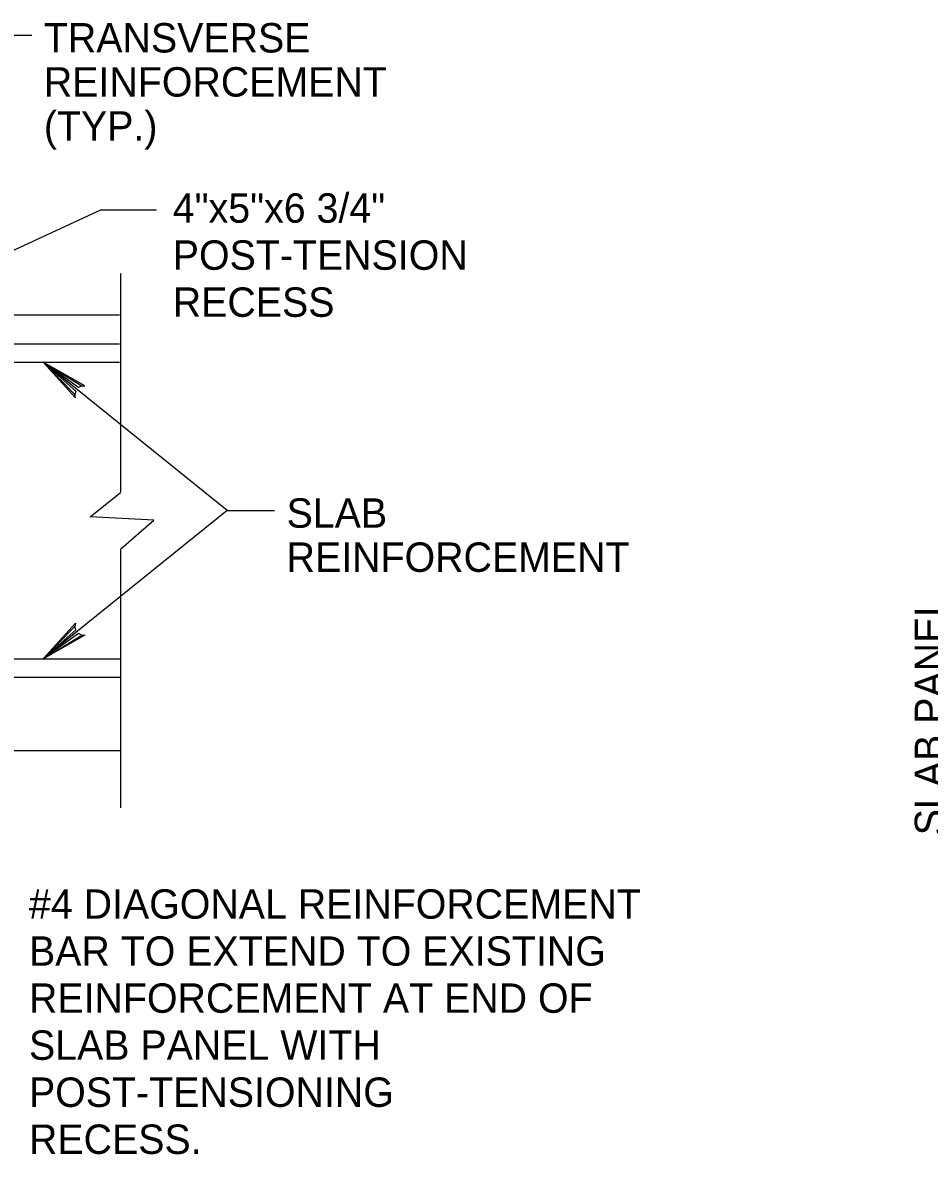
# Model space of a CAD drawing. Extents: x 641328 to 643024, y 298283 to 300065.
# Drawn here: x 642451.6 to 642544.1, y 299655 to 299770.5 of the extents above; entities that cross this region are included whole.
import ezdxf

# ---------------------------------------------------------------- set-up
doc = ezdxf.new("R2010")
doc.units = 0
doc.layers.add('2', color=7, linetype='Continuous')
doc.layers.add('63', color=7, linetype='Continuous')

msp = doc.modelspace()

# ---------------------------------------------------------------- linework, layer by layer
at = {"layer": '2'}
for p, q in [((642447.71, 299769.2), (642452.53, 299769.2)), ((642459.62, 299751.39), (642400.79, 299724.2)), ((642459.62, 299751.39), (642465.25, 299751.39)), ((642461.61, 299722.57), (642461.61, 299744.89)), ((642461.47, 299740.64), (642336.36, 299740.64)), ((642369.11, 299737.7), (642461.47, 299737.7)), ((642369.11, 299735.85), (642461.47, 299735.85)), ((642472.47, 299720.7), (642453.69, 299735.85)), ((642472.47, 299720.7), (642453.69, 299705.55)), ((642472.47, 299720.7), (642477.29, 299720.7)), ((642461.61, 299690.35), (642461.61, 299716.78)), ((642338.24, 299705.55), (642461.61, 299705.55)), ((642338.24, 299703.7), (642461.61, 299703.7)), ((642402.39, 299696.2), (642461.61, 299696.2))]:
    msp.add_line(p, q, dxfattribs=at)
for points in [[(642457.64, 299733.41), (642457.3, 299733.25), (642453.69, 299735.85), (642457.64, 299733.41), (642457.95, 299733.41), (642453.69, 299735.85), (642457.01, 299732.89), (642456.92, 299732.54), (642453.69, 299735.85), (642456.98, 299732.21), (642456.92, 299732.54)], [(642457.64, 299707.99), (642457.3, 299708.15), (642453.69, 299705.55), (642457.64, 299707.99), (642457.95, 299707.99), (642453.69, 299705.55), (642457.01, 299708.51), (642456.92, 299708.87), (642453.69, 299705.55), (642456.98, 299709.19), (642456.92, 299708.87)]]:
    msp.add_lwpolyline(points, dxfattribs=at)
at = {"layer": '63'}
for p, q in [((642458.49, 299720.04), (642461.57, 299722.53)), ((642464.99, 299719.7), (642458.49, 299720.04)), ((642461.61, 299716.78), (642464.99, 299719.7))]:
    msp.add_line(p, q, dxfattribs=at)

# ---------------------------------------------------------------- texts
at = {"layer": '2'}
for s, height, p in [('TRANSVERSE', 3, (642453.76, 299767.43)), ('REINFORCEMENT ', 3, (642453.76, 299762.93)), ('(TYP.)', 3, (642453.76, 299758.43)), ('4"x5"x6 3/4" ', 2.9999, (642466.91, 299750.06)), ('POST-TENSION', 2.9999, (642466.91, 299745.26)), ('RECESS', 3, (642466.91, 299740.46)), ('SLAB', 3, (642478.52, 299718.94)), ('REINFORCEMENT ', 3, (642478.52, 299714.44)), ('#4 DIAGONAL REINFORCEMENT ', 2.9999, (642452.24, 299679.05)), ('BAR TO EXTEND TO EXISTING ', 2.9999, (642452.24, 299674.25)), ('REINFORCEMENT AT END OF ', 2.9999, (642452.24, 299669.45)), ('SLAB PANEL WITH ', 2.9999, (642452.24, 299664.65)), ('POST-TENSIONING', 2.9999, (642452.24, 299659.85)), ('RECESS. ', 3, (642452.24, 299655.05))]:
    msp.add_text(s, height=height, dxfattribs=at).set_placement(p)
at = {"layer": '63'}
msp.add_text('SLAB PANEL', height=3, rotation=90, dxfattribs=at).set_placement((642545.6, 299687.56))

doc.saveas('drawing.dxf')
